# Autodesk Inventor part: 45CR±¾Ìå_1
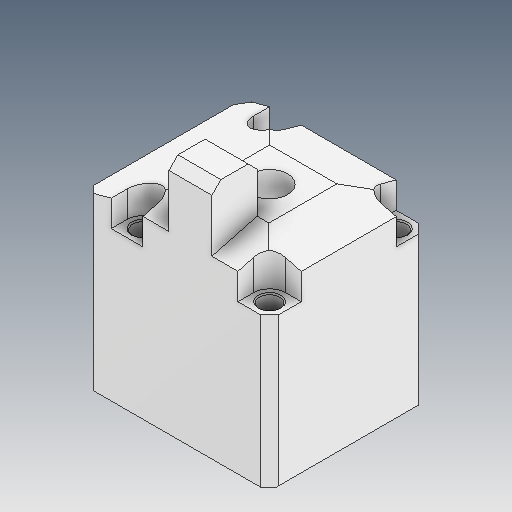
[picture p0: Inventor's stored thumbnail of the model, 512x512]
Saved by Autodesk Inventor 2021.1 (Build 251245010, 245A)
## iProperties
Created: 2021-05
Part Number: 45CR±¾Ìå_1
Material: Ogólny
Document SubType Name: Modeling
Designer: user
Density: 1 g/cm^3
Appearance: Domyślna
Author: user
Revision Number: ÈÎºÎ
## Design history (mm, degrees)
feature "NONE"
node "Bryła1"
